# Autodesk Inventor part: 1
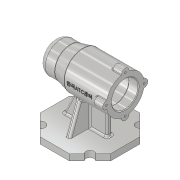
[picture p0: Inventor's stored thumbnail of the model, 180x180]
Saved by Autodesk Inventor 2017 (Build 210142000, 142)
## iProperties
Created: 2019-12
Part Number: 1
Material: 알루미늄 6061-AHC
Document SubType Name: Modeling
Designer: 5-13-le-1
Density: 2.7 g/cm^3
Appearance: 알루미늄 - 짙음
Mass: 725.066 g
Surface Area: 722.161 cm^2
Volume: 268.543 cm^3
Author: 5-13-le-1
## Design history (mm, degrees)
sketch "스케치2"
  geometry: L1 (56, -23.196)-(23.196, -56); L2 (23.196, -56)-(-23.196, -56); L3 (-23.196, -56)-(-56, -23.196); L4 (-56, -23.196)-(-56, 23.196); L5 (-56, 23.196)-(-23.196, 56); L6 (-23.196, 56)-(23.196, 56); L7 (23.196, 56)-(56, 23.196); L8 (56, 23.196)-(56, -23.196); C1 r 56 at (0, 0); 2 further points
  constraints: 16 end point, 2 coincident, 1 centre point, 1 vertical alignment, 17 other
  dimensions: "d0" = 112 diameter of C1; "d1" = 56 distance from line of L2 point (0, 0)
extrude "돌출1" new body sketch "스케치2" distance "d2" = 10; taper "d3" = 0 deg
sketch "스케치3"
  geometry: L1 (0, 0)-(-39.598, -39.598); L2 (0, 0)-(0, -29.306); L3 (0, 0)-(39.598, -39.598); C1 r 7.689 at (-39.598, -39.598); C2 r 6.56 at (39.598, -39.598); A1 r 56 centre (0, 0) between (-39.598, -39.598) and (39.598, -39.598); 1 further point
  constraints: 6 end point, 3 centre point, 2 point on circle, 1 coincident, 1 vertical
  dimensions: "d4" = 112 diameter of A1; "d5" = 45 deg angle of L2 L1; "d6" = 45 deg angle of L2 L3
extrude "돌출2" cut sketch "스케치3" stored distance "d7" = 10; taper "d8" = 0 deg
sketch "스케치4"
  geometry: L1 (-66.415, 80)-(56, 80); L2 (56, 80)-(56, 110); L3 (56, 110)-(-11, 110); L4 (-11, 110)-(-31, 105); L5 (-31, 105)-(-56, 105); L6 (-56, 105)-(-56, 80); L7 (41, 101)-(41, 104); L8 (41, 104)-(-13, 104); L9 (-13, 104)-(-13, 101); L10 (-13, 101)-(-25, 101); L11 (-25, 101)-(-25, 97.5); L12 (-25, 97.5)-(-43, 97.5); L13 (-43, 97.5)-(-43, 94.5); L14 (23.196, 0)-(34.959, 0) reference; L15 (-43, 97.5)-(-43, 96); L16 (-43, 96)-(-47, 96); L17 (-47, 96)-(-47, 90.5); L18 (-47, 90.5)-(-50, 90.5); L19 (-50, 90.5)-(-50, 80); L20 (41, 101)-(56, 101); 2 further points
  constraints: 38 end point, 10 perpendicular, 4 horizontal, 3 point on line, 1 midpoint, 1 parallel, 1 vertical, 1 vertical alignment
  dimensions: "d9" = 112 distance between parallel lines of L2 L6; "d10" = 25 distance of L4.end L5.end; "d11" = 45 distance from line of L3.end L6; "d13" = 54 distance of L7.end L8.end; "d14" = 12 distance of L9.end L10.end; "d15" = 18 distance of L11.end L12.end; "d18" = 60 diameter of L3 L1; "d19" = 80 distance between parallel lines of L14 L1; "d20" = 4 distance of L15.end L16.end; "d21" = 3 distance of L17.end L18.end; "d22" = 50 diameter of L5 L1; "d23" = 42 diameter of L20 L1; "d24" = 48 diameter of L8 L1; "d25" = 42 diameter of L10 L1; "d26" = 35 diameter of L12 L1; "d27" = 32 diameter of L16 L1; "d28" = 21 diameter of L18 L1; "d72" = 15 distance of L7.start L20.end
revolve "회전1" sketch "스케치4" stored, may be unused: angle "d29" = 90 deg
sketch "스케치5"
  geometry: L1 (10.05, -36)-(56.399, -19.13); L2 (10.05, 36)-(56.399, 19.13); L3 (10.05, 36)-(10.05, -36); L4 (10, -31.909)-(10, -45.035) reference; L5 (0, -56)-(10, -56) reference; L6 (0, 56)-(10, 56) reference; L7 (10, 45.035)-(10, 31.909) reference; L8 (56.399, 19.13)-(56.399, 18.521); L9 (56.399, -18.521)-(56.399, -19.13); C1 r 24 at (80, 0) reference; A1 r 30 centre (80, 0) between (56.399, 18.521) and (56.399, -18.521); 3 further points
  constraints: 10 end point, 2 point on circle, 2 vertical, 1 centre point, 1 coincident, 1 parallel
  dimensions: "d30" = 20 distance from line of L5 L1.start; "d31" = 20 distance from line of L2.start L6; "d32" = 110 deg angle of L4 L1; "d33" = 110 deg angle of L7 L2
extrude "돌출3" join sketch "스케치5" stored distance "d34" = 8; taper "d35" = 0 deg
sketch "스케치6"
  geometry: L1 (-45.035, 10)-(-31.909, 10) reference; L2 (-38, 10)-(-17.297, 54.398); L3 (-17.297, 54.398)-(31, 54.398); L4 (31, 54.398)-(31, 10); L5 (33.038, 10)-(44.237, 10) reference; L6 (-38, 10)-(31, 10); L7 (56, 0)-(56, 10) reference; L8 (-56, 0)-(-56, 10) reference; 3 further points
  constraints: 8 end point, 1 horizontal, 1 parallel, 1 perpendicular, 1 point on line
  dimensions: "d36" = 25 distance between parallel lines of L7 L4; "d37" = 18 distance from line of L2.start L8; "d38" = 115 deg angle of L1 L2
extrude "돌출4" join sketch "스케치6" stored distance "d39" = 8; taper "d40" = 0 deg
sketch "스케치7"
  geometry: L1 (0, 0)-(0, 30); C1 r 21 at (0, 0) reference; C2 r 6 at (0, 30); 2 further points
  constraints: 2 end point, 1 centre point, 1 coincident, 1 vertical, 1 vertical alignment, 1 other
  dimensions: "d41" = 12 diameter of C2
extrude "돌출5" join sketch "스케치7" distance "d42" = 16; taper "d43" = 0 deg
sketch "스케치8"
  geometry: A1 r 6 centre (0, 0) between (5.97, -0.6) and (-5.97, -0.6) reference; A2 r 6 centre (-30, -30) between (-29.4, -24.03) and (-29.4, -35.97) reference; A3 r 6 centre (0, -60) between (-5.97, -59.4) and (5.97, -59.4) reference; A4 r 6 centre (30, -30) between (29.4, -35.97) and (29.4, -24.03) reference; 5 further points
  constraints: 4 coincident
hole "구멍1" sketch "스케치8" at (0, 0), (-30, -30), (0, -60), (30, -30) diameter "d47" = 3.242; stored, may be unused: countersink angle "d51" = 90 deg, drill point angle "d53" = 118 deg; dims "d48" = 8, "d49" = 4, "d50" = 2, "d52" = 11
node "작업 평면1"
fillet "모깎기1" dims "d59" = 10
chamfer "모따기1" distance "d61" = 1; stored, may be unused: second distance "d62" = 2, angle "d63" = 45 deg
fillet "모깎기3" dims "d64" = 3
fillet "모깎기4" dims "d65" = 3
fillet "모깎기5" dims "d66" = 0.3
fillet "모깎기8" dims "d69" = 3
fillet "모깎기11" dims "d73" = 3
fillet "모깎기12" dims "d74" = 3
fillet "모깎기13" dims "d75" = 3
fillet "모깎기14" dims "d76" = 1
fillet "모깎기15" dims "d77" = 3
fillet "모깎기16" dims "d78" = 1
fillet "모깎기17" dims "d79" = 3
sketch "스케치10"
  geometry: L1 (45.75, 79.454)-(-18.778, 79.454); L2 (56, 86.771)-(56, 109.226) reference; 1 further point
  constraints: 2 end point, 2 horizontal
  dimensions: "d80" = 10.25 distance from line of L2 L1.start
feature "엠보싱2" sketch "스케치10" dims "d81" = 0.5, "d82" = 0
fillet "모깎기18" dims "d83" = 3
node "솔리드1"
mirror "미러1"
pattern_circular "원형 패턴1" dims angle "d45" = 360 deg
